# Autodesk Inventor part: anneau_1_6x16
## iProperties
Created: 2011-01
Part Number: anneau_1_6x16
Document SubType Name: Modeling
Designer: eric
Density: 1 g/cm^3
Mass: 0.101065 g
Surface Area: 2.52662 cm^2
Volume: 0.101065 cm^3
Author: eric
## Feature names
1. Base1
